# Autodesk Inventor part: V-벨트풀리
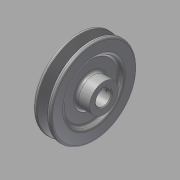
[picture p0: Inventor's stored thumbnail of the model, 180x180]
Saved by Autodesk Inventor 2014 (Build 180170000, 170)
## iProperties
Created: 2015-09
Part Number: V-벨트풀리
Material: 강철, 연강
Document SubType Name: Modeling
Designer: mduedu
Density: 7.86 g/cm^3
Mass: 779.077 g
Surface Area: 277.465 cm^2
Volume: 99.1192 cm^3
Appearance: Steel
Author: mduedu
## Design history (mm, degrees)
sketch "스케치1"
  geometry: L1 (-10, 0)-(10, 0); L2 (-10, 0)-(-10, 48); L3 (-10, 48)-(-5.976, 48); L4 (-5.976, 48)-(-2.154, 35.5); L5 (-2.154, 35.5)-(2.154, 35.5); L6 (2.154, 35.5)-(5.976, 48); L7 (5.976, 48)-(10, 48); L8 (10, 48)-(10, 0); L9 (0, 0)-(0, 35.5); L10 (-10, 43.5)-(10, 43.5); 3 further points
  constraints: 20 end point, 6 point on line, 3 perpendicular, 2 midpoint, 2 parallel, 2 symmetric about line, 1 coincident, 1 collinear, 1 equal length, 1 horizontal, 1 vertical, 1 vertical alignment
  dimensions: "d0" = 20 distance between parallel lines of L8 L2; "d2" = 96 diameter of L3 L1; "d3" = 87 diameter of L10 L1; "d4" = 4.5 distance between parallel lines of L10 L3 (derived); "d5" = 8 distance between parallel lines of L5 L10; "d6" = 9.2 distance of point (4.6, 43.5) point (-4.6, 43.5); "d7" = 34 deg angle of L6 L4
revolve "회전1" sketch "스케치1" stored, may be unused: angle "d8" = 90 deg
sketch "스케치2"
  geometry: C1 r 16 at (0, 0); 1 further point
  constraints: 1 centre point, 1 coincident
  dimensions: "d9" = 32 diameter of C1
extrude "돌출1" join sketch "스케치2" distance "d10" = 11; taper "d11" = 0 deg
fillet "모깎기1" dims "d12" = 1, "d13" = 0.5, "d14" = 2
sketch "스케치3"
  geometry: C1 r 16 at (0, 0) reference; C2 r 32 at (0, 0); 1 further point
  constraints: 1 centre point, 1 coincident
  dimensions: "d15" = 64 diameter of C2
extrude "돌출2" cut sketch "스케치3" distance "d16" = 4; taper "d17" = 0 deg
fillet "모깎기2" dims "d18" = 3
fillet "모깎기3" dims "d19" = 3
fillet "모깎기4" dims "d20" = 3
sketch "스케치4"
  geometry: C1 r 8.5 at (0, 0); 1 further point
  constraints: 1 centre point, 1 coincident
  dimensions: "d21" = 17 diameter of C1
extrude "돌출3" cut sketch "스케치4" stored distance "d22" = 4; taper "d23" = 0 deg
sketch "스케치5"
  geometry: L1 (-2.5, 8.124)-(2.5, 8.124); L2 (2.5, 8.124)-(2.5, 10.8); L3 (2.5, 10.8)-(-2.5, 10.8); L4 (-2.5, 10.8)-(-2.5, 8.124); A1 r 8.5 centre (0, 0) between (-2.5, 8.124) and (2.5, 8.124) reference; 2 further points
  constraints: 8 end point, 3 point on circle, 2 parallel, 1 horizontal, 1 perpendicular, 1 vertical alignment
  dimensions: "d24" = 5 distance of L2.end L3.end; "d26" = 19.3 distance from line of L3 point (0, -8.5)
extrude "돌출4" cut sketch "스케치5" stored distance "d27" = 4; taper "d28" = 0 deg
chamfer "모따기1" distance "d29" = 1; stored, may be unused: second distance "d30" = 2, angle "d31" = 45 deg
node "작업 평면1"
sketch "스케치6"
  geometry: L1 (-11, 16)-(-11, -16) reference; 2 further points
  constraints: 1 horizontal alignment
  dimensions: "d32" = 5 distance from line of point (-6, 0) L1
hole "구멍1" sketch "스케치6" at (-6, 0) diameter "d33" = 3.242; stored, may be unused: countersink angle "d37" = 90 deg, drill point angle "d39" = 118 deg; dims "d34" = 6, "d35" = 4, "d36" = 2, "d38" = 8
node "솔리드1"
mirror "대칭1"
